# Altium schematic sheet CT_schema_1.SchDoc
size 335 x 258 mm
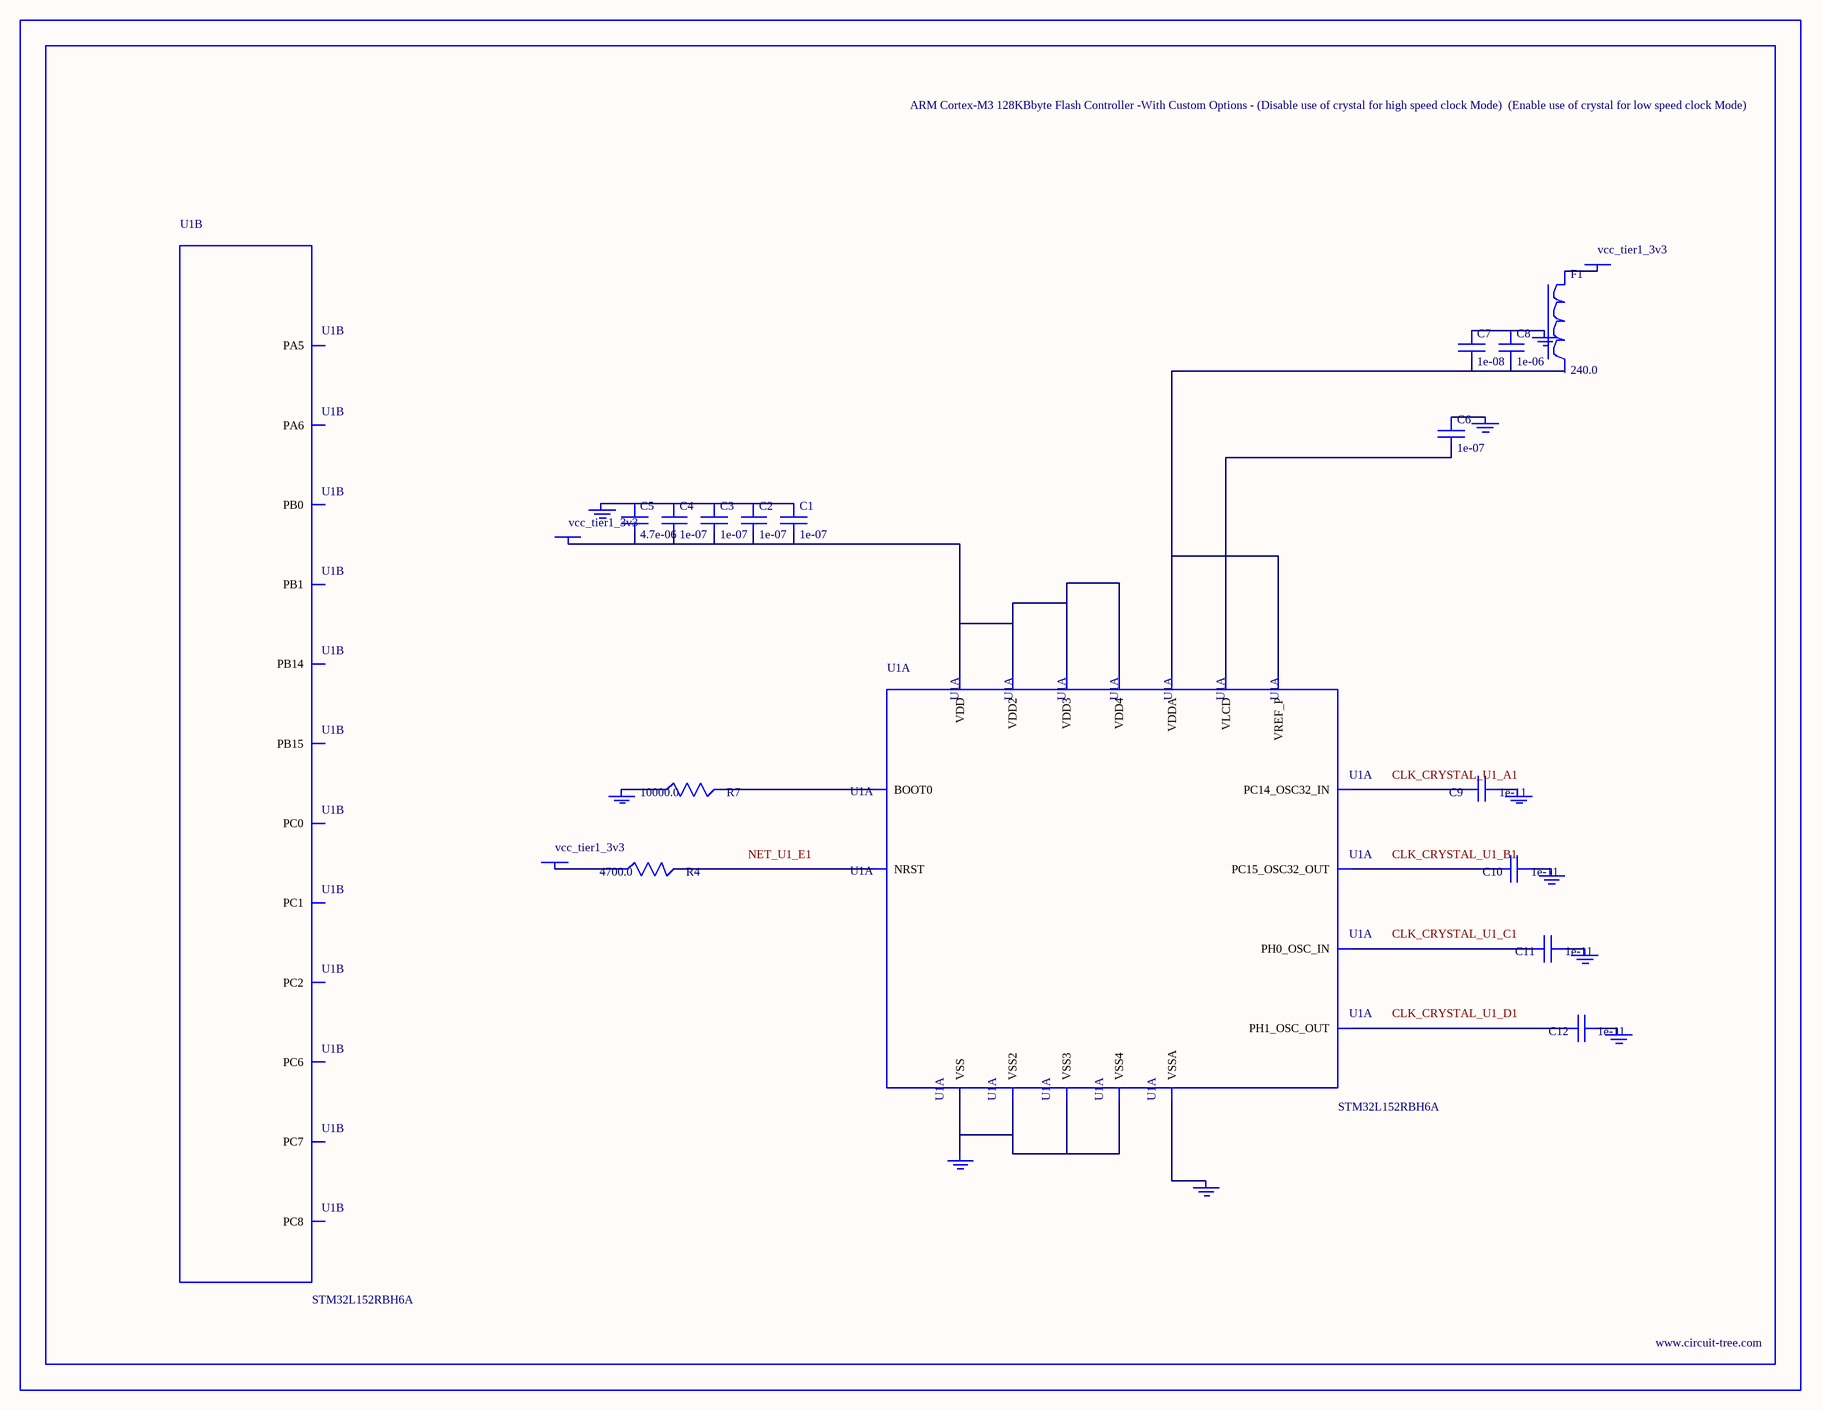
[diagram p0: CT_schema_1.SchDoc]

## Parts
BORDER0  (no value)
C1  1e-07  [C0603]
C2  1e-07  [C0603]
C3  1e-07  [C0603]
C4  1e-07  [C0603]
C5  4.7e-06  [C0603]
C6  1e-07  [C0603]
C7  1e-08  [C0603]
C8  1e-06  [C0603]
C9  1e-11  [C0402]
C10  1e-11  [C0402]
C11  1e-11  [C0402]
C12  1e-11  [C0402]
F1  240.0  [L0603]
GND_INSTANCE_0_0  (no value)
GND_INSTANCE_0_1  (no value)
GND_INSTANCE_0_2  (no value)
GND_INSTANCE_0_3  (no value)
GND_INSTANCE_0_4  (no value)
GND_INSTANCE_0_5  (no value)
GND_INSTANCE_0_6  (no value)
GND_INSTANCE_0_7  (no value)
GND_INSTANCE_0_8  (no value)
GND_INSTANCE_0_9  (no value)
POWER_INSTANCE_0_0  vcc_tier1_3v3
POWER_INSTANCE_0_1  vcc_tier1_3v3
POWER_INSTANCE_0_2  vcc_tier1_3v3
R4  4700.0  [R0603]
R7  10000.0  [R0603]
U1  STM32L152RBH6A  [TFBGA64]  (parts A,B of 7)

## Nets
NetC1_1: C1.1 C2.1 C3.1 C4.1 C5.1 GND_INSTANCE_0_1.0(GND)
NetC1_2: C1.2 C2.2 C3.2 C4.2 C5.2 POWER_INSTANCE_0_1.0(PWR) U1.D2(VDD) U1.E4(VDD2) U1.E5(VDD3) U1.E6(VDD4)
NetC6_1: C6.1 GND_INSTANCE_0_2.0(GND)
NetC6_2: C6.2 U1.B2(VLCD)
NetC7_1: C7.1 C8.1 GND_INSTANCE_0_0.0(GND)
NetC7_2: C7.2 C8.2 U1.G1(VREF_P) U1.H1(VDDA)
NetC9_1: C9.1 GND_INSTANCE_0_4.0(GND)
NetC9_2: C9.2 U1.A1(PC14_OSC32_IN)
NetC10_1: C10.1 GND_INSTANCE_0_5.0(GND)
NetC10_2: C10.2 U1.B1(PC15_OSC32_OUT)
NetC11_1: C11.1 GND_INSTANCE_0_6.0(GND)
NetC11_2: C11.2 U1.C1(PH0_OSC_IN)
NetC12_1: C12.1 GND_INSTANCE_0_7.0(GND)
NetC12_2: C12.2 U1.D1(PH1_OSC_OUT)
NetF1_1: F1.1 POWER_INSTANCE_0_0.0(PWR)
NetGND_INSTANCE_0_3_0: GND_INSTANCE_0_3.0(GND) R7.1
NetGND_INSTANCE_0_8_0: GND_INSTANCE_0_8.0(GND) U1.F1(VSSA)
NetGND_INSTANCE_0_9_0: GND_INSTANCE_0_9.0(GND) U1.C2(VSS) U1.D4(VSS2) U1.D5(VSS3) U1.D6(VSS4)
NetPOWER_INSTANCE_0_2_0: POWER_INSTANCE_0_2.0(PWR) R4.1
NetR4_2: R4.2 U1.E1(NRST)
NetR7_2: R7.2 U1.B4(BOOT0)

Not connected (* = marked no-connect by the designer): F1 2; U1 E2(PC1) E3(PC0) E7(PC7) E8(PC8) F2(PC2) F4(PA5) F5(PB0) F6(PC6) F7(PB15) F8(PB14) G4(PA6) G5(PB1)

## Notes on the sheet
- Labels drawn without touching a wire or pin: CLK_CRYSTAL_U1_A1, CLK_CRYSTAL_U1_B1, CLK_CRYSTAL_U1_C1, CLK_CRYSTAL_U1_D1, NET_U1_E1

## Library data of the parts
BORDER0 = BORDER_PAGE0
C1-C4 C6 = 06035C104K4Z2A
C5 = GRM188R6YA475KE15D
C7 = 06035C103K4Z2A
C8 = C0603C105K3RACTU
C9-C12 = C0402C100K3GACTU
F1 = Z0603C241ASMST
GND_INSTANCE_0_0-GND_INSTANCE_0_9 = GND
POWER_INSTANCE_0_0-POWER_INSTANCE_0_2 = PWR
R4 = RC0603JR-074K7L
R7 = RC0603JR-0710KL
